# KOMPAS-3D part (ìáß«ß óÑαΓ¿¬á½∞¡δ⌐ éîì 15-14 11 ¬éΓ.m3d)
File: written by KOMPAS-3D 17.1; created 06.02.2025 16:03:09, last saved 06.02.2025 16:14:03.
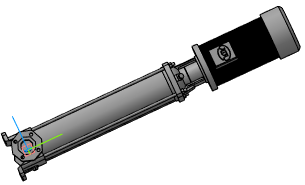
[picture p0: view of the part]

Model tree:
1. Операция без истории:1  (labels: Насос вертикальный ВМН 15-14 11 кВт)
